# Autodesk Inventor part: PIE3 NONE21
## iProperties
Shininess: 64.0
Length Units: 11269
Angle Units: 11279
Time Units: 11290
Mass Units: 11286
Length Display Precision: 3
Angle Display Precision: 2
Compacted: True
Part Number: PIE3 NONE21
Document SubType Name: Modeling
Created: 2004-08
Designer: John Blackburn
Manufacturer: Standard
Standards Organization: Custom
Density: 0.0
Volumn: 0.0
Area: 0.0
PropertySet Name: Model Information
Control State: 0
Master: False
Checked Out: False
Author: John Blackburn
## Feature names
1. Erst1
